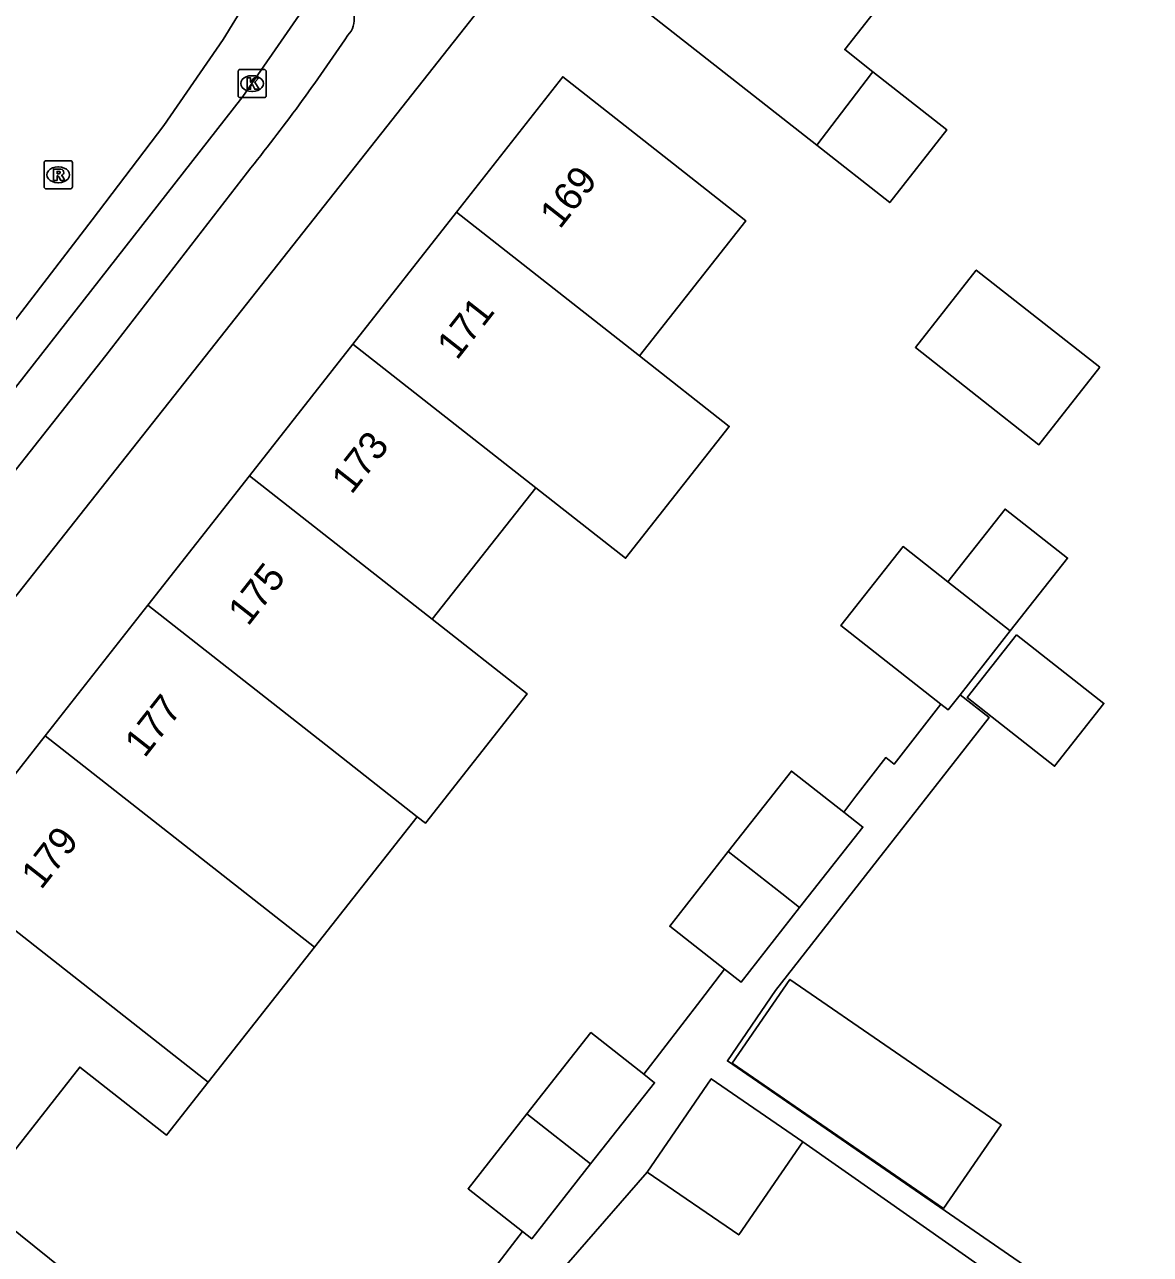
# Model space of a CAD drawing. Extents: x 160158 to 160921, y 381517 to 382041.
# Drawn here: x 160626.62 to 160666.58, y 381799.78 to 381843.43 of the extents above; entities that cross this region are included whole.
import ezdxf

# ---------------------------------------------------------------- set-up
doc = ezdxf.new("R2010")
doc.units = 0
for name, color, linetype in [('IMGEO_Kolk', 7, 'Continuous'), ('IMGEO_Pand', 7, 'Continuous'), ('IMGEO_Pand_nummerreeks', 7, 'Continuous'), ('IMGEO_Rijbaan_lokaal_gesloten', 7, 'Continuous'), ('IMGEO_Rioolput', 7, 'Continuous'), ('IMGEO_Voetpad_open', 7, 'Continuous')]:
    doc.layers.add(name, color=color, linetype=linetype)

msp = doc.modelspace()

# ---------------------------------------------------------------- linework, layer by layer
at = {"layer": 'IMGEO_Kolk'}
for p, q in [((160634.196, 381840.914), (160634.196, 381841.766)), ((160634.271, 381841.84), (160635.123, 381841.84)), ((160634.684, 381841.62), (160634.709, 381841.62)), ((160635.197, 381841.766), (160635.197, 381840.914)), ((160634.707, 381841.06), (160634.682, 381841.06)), ((160635.123, 381840.84), (160634.271, 381840.84))]:
    msp.add_line(p, q, dxfattribs=at)
for points in [[(160634.196, 381840.914), (160634.196, 381841.766)], [(160634.271, 381841.84), (160635.123, 381841.84)], [(160634.517, 381841.54), (160634.64, 381841.54), (160634.64, 381841.389), (160634.77, 381841.54), (160634.934, 381841.54), (160634.788, 381841.389), (160634.941, 381841.14), (160634.789, 381841.14), (160634.704, 381841.304), (160634.64, 381841.237), (160634.64, 381841.14), (160634.517, 381841.14), (160634.517, 381841.54)], [(160635.197, 381841.766), (160635.197, 381840.914)], [(160635.123, 381840.84), (160634.271, 381840.84)]]:
    msp.add_lwpolyline(points, dxfattribs=at)
for centre, start, end in [((160634.273, 381841.764), 91.552, 178.448), ((160634.273, 381841.764), 91.552, 178.448), ((160635.121, 381841.764), 1.552, 88.448), ((160635.121, 381841.764), 1.552, 88.448), ((160634.273, 381840.916), 181.552, 268.448), ((160634.273, 381840.916), 181.552, 268.448), ((160635.121, 381840.916), 271.552, 358.448), ((160635.121, 381840.916), 271.552, 358.448)]:
    msp.add_arc(centre, 0.0765, start, end, dxfattribs=at)
for centre, major_axis, ratio, start_param, end_param in [((160634.683, 381841.34), (-0.387, 0.002), 0.722429, 4.712389, 7.853982), ((160634.708, 381841.34), (-0.39, 0.002), 0.717154, 1.570796, 4.712389)]:
    msp.add_ellipse(centre, major_axis=major_axis, ratio=ratio, start_param=start_param, end_param=end_param, dxfattribs=at)
at = {"layer": 'IMGEO_Pand'}
for points in [[(160654.742, 381839.152), (160647.999, 381844.459), (160651.347, 381848.713), (160657.053, 381844.222), (160655.733, 381842.545), (160656.729, 381841.761)], [(160641.945, 381836.776), (160645.719, 381841.583), (160649.648, 381838.491), (160652.219, 381836.467), (160648.446, 381831.672)], [(160656.729, 381841.761), (160659.356, 381839.693), (160657.328, 381837.116), (160654.742, 381839.152)], [(160656.729, 381841.761), (160656.683, 381841.696), (160654.742, 381839.152)], [(160638.269, 381832.094), (160641.945, 381836.776)], [(160648.446, 381831.672), (160641.945, 381836.776)], [(160664.786, 381831.267), (160660.4, 381834.718), (160658.239, 381831.971), (160662.625, 381828.52), (160664.786, 381831.267)], [(160634.598, 381827.418), (160638.269, 381832.094)], [(160638.269, 381832.094), (160644.765, 381826.994)], [(160648.446, 381831.672), (160651.631, 381829.167), (160647.95, 381824.488), (160644.765, 381826.994)], [(160630.989, 381822.82), (160634.598, 381827.418)], [(160641.089, 381822.322), (160634.598, 381827.418)], [(160644.765, 381826.994), (160641.089, 381822.322)], [(160661.607, 381821.911), (160663.639, 381824.494), (160661.424, 381826.236), (160659.392, 381823.653)], [(160659.392, 381823.653), (160657.801, 381824.905), (160655.594, 381822.101), (160659.144, 381819.308)], [(160661.607, 381821.911), (160659.392, 381823.653)], [(160627.35, 381818.185), (160630.989, 381822.82)], [(160640.553, 381815.313), (160637.475, 381817.729), (160630.989, 381822.82)], [(160641.089, 381822.322), (160644.453, 381819.681), (160640.845, 381815.084), (160640.553, 381815.313)], [(160659.823, 381819.644), (160661.607, 381821.911)], [(160661.833, 381821.771), (160664.929, 381819.334), (160663.176, 381817.106), (160660.08, 381819.542), (160661.833, 381821.771)], [(160659.144, 381819.308), (160659.4, 381819.106), (160659.823, 381819.644)], [(160623.586, 381813.39), (160627.35, 381818.185)], [(160627.35, 381818.185), (160636.909, 381810.681)], [(160655.694, 381815.478), (160653.841, 381816.933), (160651.596, 381814.073)], [(160640.553, 381815.313), (160636.909, 381810.681)], [(160654.128, 381812.085), (160656.373, 381814.945), (160655.694, 381815.478)], [(160651.596, 381814.073), (160649.519, 381811.427), (160651.461, 381809.902)], [(160651.596, 381814.073), (160653.495, 381812.582), (160654.128, 381812.085)], [(160623.586, 381813.39), (160633.139, 381805.89)], [(160651.461, 381809.902), (160652.051, 381809.439), (160654.128, 381812.085)], [(160636.909, 381810.681), (160633.139, 381805.89)], [(160659.24, 381801.407), (160661.282, 381804.377), (160653.782, 381809.536), (160651.739, 381806.566), (160659.24, 381801.407)], [(160644.45, 381804.761), (160646.722, 381807.648), (160648.6, 381806.17)], [(160633.139, 381805.89), (160631.654, 381804.003), (160628.579, 381806.423), (160624.886, 381801.729)], [(160648.6, 381806.17), (160648.979, 381805.872), (160646.709, 381802.988)], [(160648.718, 381802.7), (160650.995, 381806.011), (160654.242, 381803.777)], [(160644.299, 381800.585), (160642.363, 381802.108), (160644.45, 381804.761)], [(160644.45, 381804.761), (160646.709, 381802.988)], [(160654.242, 381803.777), (160651.966, 381800.467), (160648.718, 381802.7)], [(160646.709, 381802.988), (160644.62, 381800.332), (160644.299, 381800.585)]]:
    msp.add_lwpolyline(points, dxfattribs=at)
at = {"layer": 'IMGEO_Rijbaan_lokaal_gesloten'}
for points in [[(160606.724, 381808.255), (160614.68, 381818.128), (160622.418, 381827.913), (160629.021, 381836.504), (160631.565, 381839.849), (160633.663, 381842.9), (160640.924, 381854.723), (160641.849, 381856.501)], [(160614.85, 381816.044), (160620.664, 381823.358), (160634.363, 381840.886), (160638.255, 381846.511)]]:
    msp.add_lwpolyline(points, dxfattribs=at)
at = {"layer": 'IMGEO_Rioolput'}
for p, q in [((160627.314, 381837.675), (160627.314, 381838.527)), ((160627.389, 381838.601), (160628.241, 381838.601)), ((160628.315, 381838.527), (160628.315, 381837.675)), ((160627.802, 381838.381), (160627.827, 381838.381)), ((160628.241, 381837.601), (160627.389, 381837.601)), ((160627.825, 381837.821), (160627.8, 381837.821))]:
    msp.add_line(p, q, dxfattribs=at)
for points in [[(160627.314, 381837.675), (160627.314, 381838.527)], [(160627.389, 381838.601), (160628.241, 381838.601)], [(160628.315, 381838.527), (160628.315, 381837.675)], [(160627.903, 381838.299), (160627.651, 381838.301), (160627.651, 381837.901)], [(160627.651, 381837.901), (160627.775, 381837.901), (160627.775, 381838.063), (160627.786, 381838.063)], [(160627.829, 381838.22), (160627.775, 381838.22), (160627.775, 381838.139)], [(160627.775, 381838.139), (160627.827, 381838.139)], [(160627.833, 381838.034), (160627.904, 381837.901), (160628.044, 381837.901), (160627.979, 381838.027)], [(160628.241, 381837.601), (160627.389, 381837.601)]]:
    msp.add_lwpolyline(points, dxfattribs=at)
for centre, radius, start, end in [((160627.391, 381838.525), 0.0765, 91.552, 178.448), ((160627.391, 381838.525), 0.0765, 91.552, 178.448), ((160628.239, 381838.525), 0.0765, 1.552, 88.448), ((160628.239, 381838.525), 0.0765, 1.552, 88.448), ((160627.785, 381838.01), 0.0533, 26.0293, 88.6989), ((160627.811, 381838.328), 0.19, 274.7715, 282.9687), ((160627.835, 381838.124), 0.0964, 77.0061, 93.1865), ((160627.849, 381838.181), 0.0378, 276.6634, 79.6772), ((160627.902, 381838.189), 0.109, 350.3612, 89.416), ((160627.9, 381838.189), 0.112, 277.5842, 350.9817), ((160627.884, 381837.974), 0.108, 29.5134, 73.7905), ((160627.391, 381837.677), 0.0765, 181.552, 268.448), ((160627.391, 381837.677), 0.0765, 181.552, 268.448), ((160628.239, 381837.677), 0.0765, 271.552, 358.448), ((160628.239, 381837.677), 0.0765, 271.552, 358.448)]:
    msp.add_arc(centre, radius, start, end, dxfattribs=at)
for centre, major_axis, ratio, start_param, end_param in [((160627.801, 381838.101), (-0.387, 0.002), 0.722429, 4.712389, 7.853982), ((160627.826, 381838.101), (-0.39, 0.002), 0.717154, 1.570796, 4.712389)]:
    msp.add_ellipse(centre, major_axis=major_axis, ratio=ratio, start_param=start_param, end_param=end_param, dxfattribs=at)
at = {"layer": 'IMGEO_Voetpad_open'}
for points in [[(160664.857, 381866.115), (160662.715, 381866.57), (160660.296, 381866.624), (160658.571, 381866.17), (160657.082, 381865.462), (160655.682, 381864.592), (160655.188, 381864.027), (160654.415, 381863.144), (160653.212, 381861.298), (160647.699, 381851.584), (160644.987, 381846.807), (160615.493, 381809.458), (160615.388, 381809.332)], [(160634.532, 381838.199), (160629.501, 381831.69), (160617.781, 381816.821)], [(160659.823, 381819.644), (160660.862, 381818.835), (160653.268, 381809.14), (160651.567, 381806.643), (160675.928, 381789.86)], [(160655.694, 381815.478), (160656.12, 381816.04), (160657.189, 381817.412), (160657.486, 381817.18), (160659.144, 381819.308)], [(160648.6, 381806.17), (160650.628, 381808.804), (160651.461, 381809.902)], [(160675.328, 381788.989), (160654.242, 381803.777)], [(160648.718, 381802.7), (160643.768, 381797.021), (160642.365, 381795.237), (160640.014, 381792.247), (160637.708, 381789.314), (160623.85, 381800.698)], [(160624.886, 381801.729), (160632.65, 381795.49)], [(160640.007, 381795.011), (160644.299, 381800.585)]]:
    msp.add_lwpolyline(points, dxfattribs=at)
for centre, radius, start, end in [((160637.493, 381843.624), 0.831, 316.5022, 9.0405), ((160579.887, 381882.065), 70.073, 321.24443, 326.16912)]:
    msp.add_arc(centre, radius, start, end, dxfattribs=at)

# ---------------------------------------------------------------- texts
at = {"layer": 'IMGEO_Pand_nummerreeks'}
for s, rotation, p in [('169', 51.866, (160645.617, 381836.142)), ('171', 51.866, (160641.965, 381831.489)), ('173', 51.866, (160638.222, 381826.722)), ('175', 51.8641, (160634.551, 381822.046)), ('177', 51.8641, (160630.879, 381817.369)), ('179', 51.866, (160627.207, 381812.691))]:
    msp.add_text(s, height=1, rotation=rotation, dxfattribs=at).set_placement(p)

doc.saveas('drawing.dxf')
